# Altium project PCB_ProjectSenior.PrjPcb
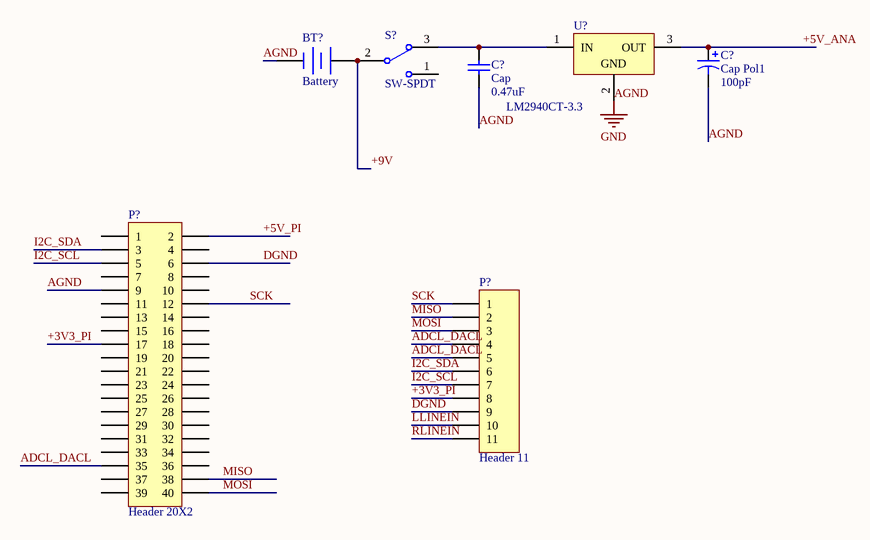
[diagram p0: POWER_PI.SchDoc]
2 sheets, 7 parts. Net scope: global (net labels, ports and power ports of the same name join across sheets).
Sheets:
  POWER_PI.SchDoc
  CODEC_INTERFACE.SchDoc

## Sheet POWER_PI.SchDoc
size A; SheetNumber: 1; SheetTotal: 2

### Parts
(Parts that share a designator on the sheet are numbered #1, #2 ... from top to bottom, then left to right.)
BT?  Battery  [BAT-2]
C?#1  Cap Pol1  value 100pF  [RB7.6-15]
C?#2  Cap  value 0.47uF  [RAD-0.3]
P?#1  Header 20X2  [HDR2X20]
P?#2  Header 11  [HDR1X11]
S?  SW-SPDT  [SW DPST jameco]
U?  LM2940CT-3.3  [T03B]

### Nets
AGND: BT?.2(-) C?#1.2 C?#2.1 P?#1.9 U?.2(GND)  [also labelled GND]
+3V3_PI: P?#1.17 P?#2.8
+5V_ANA: C?#1.1 U?.3(OUT)
+5V_PI: P?#1.2
+9V: BT?.1(+) S?.2
ADCL_DACL: P?#1.35 P?#2.4 P?#2.5
DGND: P?#1.6 P?#2.9
I2C_SCL: P?#1.5 P?#2.7
I2C_SDA: P?#1.3 P?#2.6
LLINEIN: P?#2.10
MISO: P?#1.38 P?#2.2
MOSI: P?#1.40 P?#2.3
RLINEIN: P?#2.11
SCK: P?#1.12 P?#2.1
NetC?#2_2: C?#2.2 S?.3 U?.1(IN)

Not connected (* = marked no-connect by the designer): P?#1 1 4 7 8 10 11 13 14 15 16 18 19 20 21 22 23 24 25 26 27 28 29 30 31 32 33 34 36 37 39; S? 1

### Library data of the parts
BT? = Battery: Multicell Battery
C?#1 = Cap Pol1: Polarized Capacitor (Radial)
C?#2 = Cap: Capacitor
P?#1 = Header 20X2: Header, 20-Pin, Dual row
P?#2 = Header 11: Header, 11-Pin
S? = SW-SPDT: SPDT Subminiature Toggle Switch, Right Angle Mounting, Vertical Actuation
U? = LM2940CT-5.0: 1A Low Dropout Regulator, 3-pin TO-220; Manufacturer: National Semiconductor; PackageTopMarking: NSUZXYTTE#*LM2940CT*-5.0 P+; PowerWise: N; CompType: LDO IC; High-Reliability: Y

## Sheet CODEC_INTERFACE.SchDoc
size A; SheetNumber: 2; SheetTotal: 2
